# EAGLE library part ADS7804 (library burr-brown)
12-Bit 10us Sampling CMOS ADC
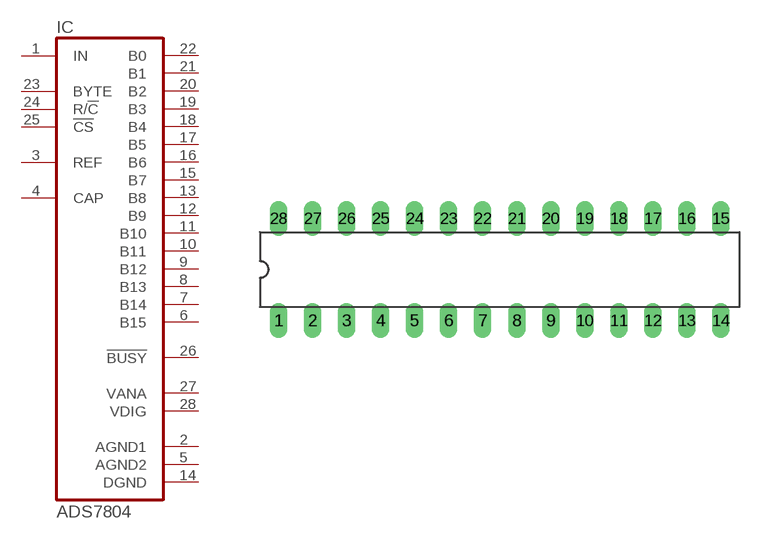
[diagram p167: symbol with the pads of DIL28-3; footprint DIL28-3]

Designator prefix IC

## ADS7804P (MF: TEXAS INSTRUMENTS; MPN: ADS7804P; OC_FARNELL: unknown; OC_NEWARK: 35C1525)  [DIL28-3]
1  IN  in
2  AGND1  pwr
3  REF
4  CAP  pas
5  AGND2  pwr
6  B15  out
7  B14  out
8  B13  out
9  B12  out
10  B11  out
11  B10  out
12  B9  out
13  B8  out
14  DGND  pwr
15  B7  out
16  B6  out
17  B5  out
18  B4  out
19  B3  out
20  B2  out
21  B1  out
22  B0  out
23  BYTE  in
24  R/!C  in
25  !CS  in
26  !BUSY  out
27  VANA  pwr
28  VDIG  pwr

## Footprint DIL28-3 (pad centres in mm)
Dual In Line 0.3 inch
drill 0.813 long: 1 -16.51,-3.81; 2 -13.97,-3.81; 3 -11.43,-3.81; 4 -8.89,-3.81; 5 -6.35,-3.81; 6 -3.81,-3.81; 7 -1.27,-3.81; 8 1.27,-3.81; 9 3.81,-3.81; 10 6.35,-3.81; 11 8.89,-3.81; 12 11.43,-3.81; 13 13.97,-3.81; 14 16.51,-3.81; 15 16.51,3.81; 16 13.97,3.81; 17 11.43,3.81; 18 8.89,3.81; 19 6.35,3.81; 20 3.81,3.81; 21 1.27,3.81; 22 -1.27,3.81; 23 -3.81,3.81; 24 -6.35,3.81; 25 -8.89,3.81; 26 -11.43,3.81; 27 -13.97,3.81; 28 -16.51,3.81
